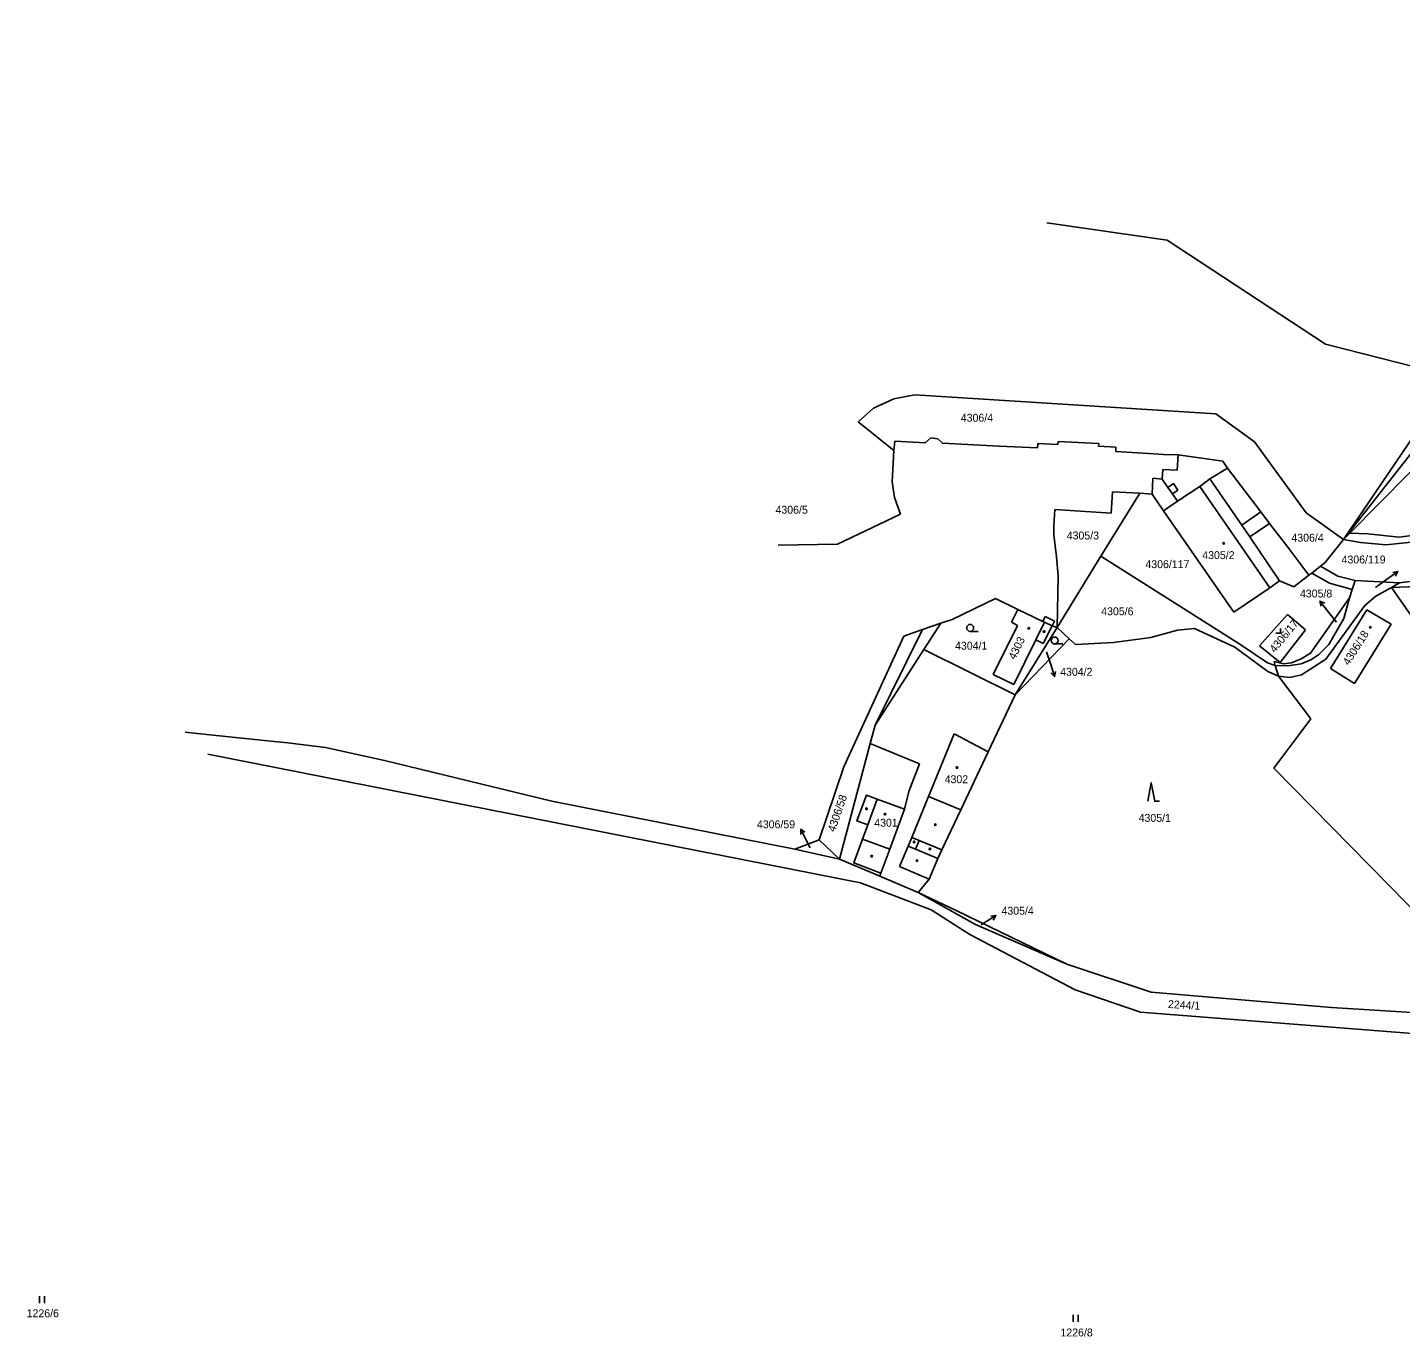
# Model space of a CAD drawing. Extents: x -717507 to -715515, y -957700 to -954941.
# Drawn here: x -717216.2 to -716920.4, y -956686.4 to -956404.4 of the extents above; entities that cross this region are included whole.
import ezdxf

# ---------------------------------------------------------------- set-up
doc = ezdxf.new("R2010")
doc.units = 0
for name, color, linetype in [('Hranice kat_území', 7, 'Continuous'), ('Hranice parcel', 7, 'Continuous'), ('Parcelní čísla', 7, 'Continuous'), ('Pop  PČ popisy', 7, 'Continuous'), ('Vnitřní kresba', 7, 'Continuous'), ('Značky budov', 7, 'Continuous'), ('Značky kultur', 7, 'Continuous')]:
    doc.layers.add(name, color=color, linetype=linetype)

msp = doc.modelspace()

# ---------------------------------------------------------------- linework, layer by layer
at = {"layer": 'Hranice kat_území'}
for points in [[(-717182.2, -956556.2), (-717176.91, -956556.79)], [(-717176.91, -956556.79), (-717168.53, -956557.66)], [(-717168.53, -956557.66), (-717163.78, -956558.15)], [(-717163.78, -956558.15), (-717160.1, -956558.51)], [(-717160.1, -956558.51), (-717152, -956559.57)], [(-717152, -956559.57), (-717139.29, -956562.3)], [(-717139.29, -956562.3), (-717103.19, -956571.1)], [(-717103.19, -956571.1), (-717050.85, -956581.44)], [(-717050.85, -956581.44), (-717041.23, -956583.58)], [(-717041.23, -956583.58), (-717032.56, -956587.24)], [(-717032.56, -956587.24), (-717024.26, -956590.75)], [(-717024.26, -956590.75), (-717011.91, -956597.67)], [(-717011.91, -956597.67), (-716992.25, -956606.23)], [(-716992.25, -956606.23), (-716974.1, -956612.22)], [(-716974.1, -956612.22), (-716935.21, -956615.54)], [(-716935.21, -956615.54), (-716905.16, -956617.42)]]:
    msp.add_lwpolyline(points, dxfattribs=at)
at = {"layer": 'Hranice parcel'}
for points in [[(-716996.56, -956446.46), (-716970.67, -956450.24)], [(-716970.67, -956450.24), (-716936.51, -956472.61)], [(-716936.51, -956472.61), (-716908.87, -956479.65)], [(-716932.64, -956514.75), (-716908.87, -956479.65)], [(-717029.51, -956484.4), (-717025.03, -956483.57)], [(-717025.03, -956483.57), (-716960.17, -956487.66)], [(-717037.23, -956489.38), (-717033.89, -956486.4)], [(-717033.89, -956486.4), (-717029.51, -956484.4)], [(-717037.23, -956489.38), (-717029.51, -956495.58)], [(-716960.17, -956487.66), (-716951.83, -956493.67)], [(-717029.87, -956502.33), (-717029.51, -956495.58)], [(-717029.51, -956495.58), (-717029.3, -956493.53)], [(-717029.3, -956493.53), (-717022.8, -956493.87)], [(-717022.8, -956493.87), (-717021.54, -956492.85)], [(-717021.54, -956492.85), (-717020.03, -956493.02)], [(-717020.03, -956493.02), (-717019.02, -956493.95)], [(-717019.02, -956493.95), (-717006.87, -956494.63)], [(-717006.87, -956494.63), (-716998.6, -956494.98)], [(-716998.6, -956494.98), (-716998.49, -956494.04)], [(-716998.49, -956494.04), (-716994.19, -956494.23)], [(-716994.19, -956494.23), (-716994.16, -956493.63)], [(-716994.16, -956493.63), (-716985.4, -956494.03)], [(-716985.42, -956494.63), (-716985.4, -956494.03)], [(-716985.42, -956494.63), (-716981.67, -956494.8)], [(-716981.73, -956495.79), (-716981.67, -956494.8)], [(-716951.83, -956493.67), (-716940.7, -956508.96)], [(-716931.26, -956513.35), (-716912.39, -956494.22)], [(-716981.73, -956495.79), (-716973.51, -956496.26)], [(-716973.51, -956496.26), (-716971.44, -956496.43)], [(-716971.44, -956496.43), (-716968.28, -956496.47)], [(-716968.51, -956499.79), (-716968.28, -956496.47)], [(-716968.28, -956496.47), (-716958.65, -956497.84)], [(-716958.65, -956497.84), (-716957.64, -956499.36)], [(-716971.73, -956501.72), (-716971.57, -956499.61)], [(-716971.57, -956499.61), (-716968.51, -956499.79)], [(-716957.64, -956499.36), (-716950.48, -956508.76)], [(-717029.87, -956502.33), (-717029.35, -956505.7)], [(-716982.71, -956509.07), (-716982.45, -956504.42)], [(-716982.45, -956504.42), (-716976.56, -956504.75)], [(-716973.85, -956504.96), (-716973.71, -956501.54)], [(-716973.71, -956501.54), (-716971.73, -956501.72)], [(-717029.35, -956505.7), (-717028.07, -956509.25)], [(-716976.56, -956504.75), (-716984.91, -956518.33)], [(-716976.56, -956504.75), (-716973.85, -956504.96)], [(-716973.85, -956504.96), (-716971.4, -956508.52)], [(-717041.69, -956515.75), (-717028.07, -956509.25)], [(-716995.08, -956511.7), (-716994.82, -956508.26)], [(-716994.82, -956508.26), (-716982.71, -956509.07)], [(-716971.4, -956508.52), (-716956.28, -956530.38)], [(-716950.48, -956508.76), (-716948.59, -956511.24)], [(-716940.7, -956508.96), (-716932.64, -956514.75)], [(-716995.08, -956511.7), (-716995.08, -956513.74)], [(-716948.59, -956511.24), (-716944.66, -956516.4)], [(-716932.64, -956514.75), (-716931.26, -956513.35)], [(-716931.26, -956513.35), (-716927.38, -956513.49)], [(-716920.68, -956514.21), (-716911.98, -956513.08)], [(-717054.43, -956515.95), (-717041.69, -956515.75)], [(-716995.08, -956513.74), (-716994.51, -956518.44)], [(-716936.68, -956519.78), (-716932.64, -956514.75)], [(-716927.38, -956513.49), (-716920.68, -956514.21)], [(-716994.51, -956518.44), (-716994.13, -956522.62)], [(-716984.91, -956518.33), (-716994.36, -956533.7)], [(-716984.91, -956518.33), (-716954.99, -956537.24)], [(-716944.66, -956516.4), (-716940.12, -956522.43)], [(-716940.12, -956522.43), (-716939.5, -956521.95)], [(-716939.5, -956521.95), (-716937.58, -956520.45)], [(-716939.5, -956521.95), (-716935.64, -956524.14)], [(-716937.58, -956520.45), (-716936.68, -956519.78)], [(-716994.36, -956533.7), (-716994.13, -956522.62)], [(-716956.28, -956530.38), (-716948.56, -956525.1)], [(-716948.56, -956525.1), (-716946.47, -956523.59)], [(-716946.47, -956523.59), (-716943.35, -956524.91)], [(-716943.35, -956524.91), (-716940.12, -956522.43)], [(-716935.64, -956524.14), (-716930.77, -956525.47)], [(-716930.77, -956525.47), (-716930.12, -956523.58)], [(-716930.12, -956523.58), (-716920.58, -956524.04)], [(-716925.7, -956526.95), (-716922.32, -956525.03)], [(-716922.32, -956525.03), (-716920.58, -956524.04)], [(-716922.32, -956525.03), (-716909.57, -956524.59)], [(-716887.95, -956574.29), (-716922.32, -956525.03)], [(-717016.95, -956531.93), (-717007.65, -956527.44)], [(-717007.65, -956527.44), (-717002.78, -956529.78)], [(-716939.75, -956539.21), (-716931.38, -956527.27)], [(-716932.61, -956531.72), (-716931.38, -956527.27)], [(-716931.38, -956527.27), (-716930.77, -956525.47)], [(-716928.03, -956528.93), (-716925.7, -956526.95)], [(-717004.21, -956532.54), (-717002.78, -956529.78)], [(-717002.78, -956529.78), (-716997.42, -956532.36)], [(-716950.78, -956537.62), (-716944.69, -956530.91)], [(-716944.69, -956530.91), (-716940.81, -956534.16)], [(-716936.49, -956540.53), (-716928.03, -956528.93)], [(-716935.49, -956542.52), (-716927.65, -956529.84)], [(-716927.65, -956529.84), (-716922.42, -956532.99)], [(-717023.34, -956534.08), (-717019.39, -956532.75)], [(-717019.39, -956532.75), (-717016.95, -956531.93)], [(-717008.1, -956543.79), (-717002.88, -956533.23)], [(-717004.21, -956532.54), (-717002.88, -956533.23)], [(-717003.4, -956548.2), (-716994.36, -956533.7)], [(-716997.42, -956532.36), (-716996.93, -956531.33)], [(-716997.33, -956537.11), (-716995.44, -956533.31)], [(-716996.93, -956531.33), (-716994.95, -956532.29)], [(-716995.44, -956533.31), (-716994.95, -956532.29)], [(-716995.44, -956533.31), (-716994.36, -956533.7)], [(-716994.36, -956533.7), (-716991.72, -956536.15)], [(-716968.43, -956534.24), (-716964.76, -956533.88)], [(-716964.76, -956533.88), (-716956.1, -956537.93)], [(-716935.8, -956537.32), (-716932.61, -956531.72)], [(-716930.28, -956545.74), (-716922.42, -956532.99)], [(-717040.28, -956563.7), (-717027.41, -956535.53)], [(-717033.56, -956554.69), (-717023.34, -956534.08)], [(-717027.41, -956535.53), (-717023.34, -956534.08)], [(-717003.7, -956545.96), (-716998.92, -956536.32)], [(-717003.4, -956548.2), (-716991.72, -956536.15)], [(-716998.92, -956536.32), (-716997.33, -956537.11)], [(-716991.72, -956536.15), (-716990.42, -956537.32)], [(-716990.42, -956537.32), (-716982.18, -956536.93)], [(-716982.18, -956536.93), (-716974.15, -956535.83)], [(-716974.15, -956535.83), (-716968.43, -956534.24)], [(-716946.32, -956541.22), (-716940.81, -956534.16)], [(-717033.56, -956554.69), (-717023.07, -956538.44)], [(-717023.07, -956538.44), (-717003.4, -956548.2)], [(-716956.1, -956537.93), (-716948.94, -956543.19)], [(-716954.99, -956537.24), (-716949, -956541.28)], [(-716950.78, -956537.62), (-716946.32, -956541.22)], [(-716941.76, -956540.46), (-716939.75, -956539.21)], [(-716939.7, -956540.67), (-716938.05, -956539.59)], [(-716938.05, -956539.59), (-716935.8, -956537.32)], [(-716949, -956541.28), (-716947.35, -956541.85)], [(-716947.6, -956541.02), (-716945.55, -956541.53)], [(-716947.6, -956541.02), (-716947.35, -956541.85)], [(-716947.35, -956541.85), (-716947.2, -956541.9)], [(-716947.35, -956541.85), (-716946.67, -956544.15)], [(-716947.2, -956541.9), (-716944.63, -956541.96)], [(-716945.55, -956541.53), (-716943.88, -956541.28)], [(-716944.63, -956541.96), (-716941.78, -956541.51)], [(-716943.88, -956541.28), (-716941.76, -956540.46)], [(-716941.78, -956541.51), (-716939.7, -956540.67)], [(-716941.68, -956543.85), (-716936.49, -956540.53)], [(-716935.49, -956542.52), (-716930.28, -956545.74)], [(-717008.1, -956543.79), (-717003.7, -956545.96)], [(-716948.94, -956543.19), (-716946.67, -956544.15)], [(-716946.67, -956544.15), (-716939.7, -956553.33)], [(-716946.67, -956544.15), (-716944.21, -956544.44)], [(-716944.21, -956544.44), (-716941.68, -956543.85)], [(-717009.21, -956560.47), (-717003.4, -956548.2)], [(-717033.56, -956554.69), (-717034.61, -956558.65)], [(-716947.67, -956564), (-716939.7, -956553.33)], [(-717034.61, -956558.65), (-717041.23, -956583.58)], [(-717034.61, -956558.65), (-717023.97, -956563.05)], [(-717015.11, -956572.93), (-717009.21, -956560.47)], [(-717177.33, -956560.98), (-717036.7, -956588.67)], [(-717023.97, -956563.05), (-717026.29, -956569.02)], [(-717045.65, -956579.42), (-717040.28, -956563.7)], [(-716902.29, -956610.17), (-716947.67, -956564)], [(-717026.29, -956569.02), (-717027.23, -956572.85)], [(-717030.41, -956581.43), (-717027.23, -956572.85)], [(-717019.21, -956581.6), (-717015.11, -956572.93)], [(-717050.85, -956581.44), (-717045.65, -956579.42)], [(-717045.65, -956579.42), (-717041.23, -956583.58)], [(-717032.31, -956586.58), (-717030.41, -956581.43)], [(-717021.92, -956587.92), (-717020.02, -956583.47)], [(-717020.02, -956583.47), (-717019.21, -956581.6)], [(-717032.31, -956586.58), (-717032.56, -956587.24)], [(-717036.7, -956588.67), (-717021.5, -956594.54)], [(-717024.26, -956590.75), (-717021.92, -956587.92)], [(-717024.26, -956590.75), (-717016.07, -956594.62)], [(-717021.5, -956594.54), (-717013.15, -956599.83)], [(-717016.07, -956594.62), (-716992.25, -956606.23)], [(-717013.15, -956599.83), (-716990.46, -956611.71)], [(-716990.46, -956611.71), (-716976.38, -956616.58)], [(-716976.38, -956616.58), (-716882.08, -956623.93)]]:
    msp.add_lwpolyline(points, dxfattribs=at)
at = {"layer": 'Pop  PČ popisy'}
for points in [[(-716923.37, -956523.37), (-716920.93, -956521.62)], [(-716922.03, -956521.8), (-716920.93, -956521.62), (-716921.45, -956522.61)], [(-716925.73, -956525.06), (-716923.37, -956523.37)], [(-716935.86, -956530.35), (-716937.72, -956528)], [(-716937.49, -956529.09), (-716937.72, -956528), (-716936.71, -956528.47)], [(-716934.16, -956532.5), (-716935.86, -956530.35)], [(-716996.61, -956538.91), (-716995.81, -956541.41)], [(-716995.81, -956541.41), (-716994.9, -956544.27)], [(-716994.73, -956543.16), (-716994.9, -956544.27), (-716995.68, -956543.47)], [(-717048.25, -956579.82), (-717049.6, -956577.14)], [(-717049.6, -956578.26), (-717049.6, -956577.14), (-717048.7, -956577.81)], [(-717047.57, -956581.17), (-717048.25, -956579.82)], [(-717010.08, -956597.34), (-717007.53, -956595.76)], [(-717008.64, -956595.86), (-717007.53, -956595.76), (-717008.12, -956596.71)], [(-717010.68, -956597.71), (-717010.08, -956597.34)]]:
    msp.add_lwpolyline(points, dxfattribs=at)
at = {"layer": 'Vnitřní kresba'}
for points in [[(-716932.64, -956514.75), (-716846.05, -956404.4)], [(-716961.44, -956501.67), (-716957.64, -956499.36)], [(-716971.73, -956501.72), (-716970.48, -956503.51)], [(-716970.48, -956503.51), (-716969.3, -956502.68)], [(-716970.48, -956503.51), (-716969.52, -956504.89)], [(-716969.52, -956504.89), (-716968.34, -956504.07)], [(-716969.3, -956502.68), (-716968.34, -956504.07)], [(-716968.42, -956506.48), (-716963.57, -956503.28)], [(-716963.57, -956503.28), (-716961.44, -956501.67)], [(-716963.57, -956503.28), (-716948.56, -956525.1)], [(-716961.44, -956501.67), (-716954.59, -956511.65)], [(-716971.4, -956508.52), (-716968.42, -956506.48)], [(-716969.52, -956504.89), (-716968.42, -956506.48)], [(-716954.59, -956511.65), (-716950.48, -956508.76)], [(-716954.59, -956511.65), (-716952.85, -956514.18)], [(-716952.85, -956514.18), (-716948.59, -956511.24)], [(-716952.85, -956514.18), (-716946.47, -956523.59)], [(-716932.64, -956514.75), (-716929.01, -956515.36)], [(-716929.01, -956515.36), (-716923.46, -956515.86)], [(-716923.46, -956515.86), (-716910.56, -956514.53)], [(-716937.58, -956520.45), (-716933.91, -956522.61)], [(-716920.58, -956524.04), (-716901.02, -956521.58)], [(-716933.91, -956522.61), (-716930.12, -956523.58)], [(-717023.07, -956538.44), (-717019.39, -956532.75)], [(-716998.92, -956536.32), (-716997.04, -956532.54)], [(-716997.42, -956532.36), (-716997.04, -956532.54)], [(-716997.04, -956532.54), (-716995.44, -956533.31)], [(-717022.08, -956570.08), (-717016.53, -956556.62)], [(-717016.53, -956556.62), (-717009.21, -956560.47)], [(-717033.1, -956570.68), (-717035.43, -956569.82), (-717037.47, -956575.35), (-717035.15, -956576.22)], [(-717035.15, -956576.22), (-717033.1, -956570.68)], [(-717027.23, -956572.85), (-717033.1, -956570.68)], [(-717025.66, -956578.93), (-717022.08, -956570.08)], [(-717022.08, -956570.08), (-717015.11, -956572.93)], [(-717035.15, -956576.22), (-717036.27, -956579.27)], [(-717036.27, -956579.27), (-717038.18, -956584.41), (-717032.31, -956586.58)], [(-717036.27, -956579.27), (-717030.41, -956581.43)], [(-717028.32, -956585.18), (-717026.44, -956580.79)], [(-717026.44, -956580.79), (-717025.66, -956578.93)], [(-717026.44, -956580.79), (-717024.86, -956581.45)], [(-717025.66, -956578.93), (-717024.08, -956579.59)], [(-717024.86, -956581.45), (-717024.08, -956579.59)], [(-717024.08, -956579.59), (-717019.21, -956581.6)], [(-717024.86, -956581.45), (-717020.02, -956583.47)], [(-717028.32, -956585.18), (-717021.92, -956587.92)]]:
    msp.add_lwpolyline(points, dxfattribs=at)
at = {"layer": 'Značky budov'}
for centre in [(-716958.48, -956515.53), (-717000.45, -956533.85), (-716926.87, -956533.66), (-716997.15, -956534.55), (-717015.92, -956563.85), (-717035.42, -956572.74), (-717031.45, -956573.9), (-717020.58, -956576.14), (-717025.15, -956579.88), (-717021.76, -956581.42), (-717034.3, -956582.95), (-717024.53, -956583.93)]:
    msp.add_circle(centre, 0.175, dxfattribs=at)
at = {"layer": 'Značky kultur'}
for points in [[(-716947.23, -956534.91), (-716946.23, -956534.91), (-716946.23, -956533.91)], [(-717013.08, -956534.51), (-717011.33, -956534.51)], [(-716994.89, -956537.23), (-716993.14, -956537.23)], [(-716974.82, -956571.13), (-716974.07, -956567.13), (-716973.32, -956571.13), (-716972.32, -956571.13)], [(-717213.58, -956679.23), (-717213.58, -956677.73)], [(-717212.54, -956679.23), (-717212.54, -956677.73)], [(-716990.88, -956683.28), (-716990.88, -956681.78)], [(-716989.84, -956683.28), (-716989.84, -956681.78)]]:
    msp.add_lwpolyline(points, dxfattribs=at)
for centre in [(-717013.08, -956533.76), (-716994.89, -956536.48)]:
    msp.add_circle(centre, 0.75, dxfattribs=at)

# ---------------------------------------------------------------- texts
at = {"layer": 'Parcelní čísla'}
for s, p in [('4306/4', (-717015.1, -956489.33)), ('4306/5', (-717055.02, -956509.16)), ('4305/3', (-716992.28, -956514.71)), ('4306/4', (-716943.87, -956515.18)), ('4306/117', (-716975.33, -956520.89)), ('4305/2', (-716963.08, -956518.94)), ('4306/119', (-716933.07, -956519.88)), ('4305/8', (-716942.03, -956527.21)), ('4305/6', (-716984.85, -956531.04)), ('4304/1', (-717016.34, -956538.45)), ('4304/2', (-716993.69, -956544.07)), ('4302', (-717018.58, -956567.22)), ('4306/59', (-717059.02, -956576.94)), ('4301', (-717033.75, -956576.59)), ('4305/1', (-716976.79, -956575.55)), ('4305/4', (-717006.33, -956595.56)), ('1226/6', (-717216.35, -956682.29)), ('1226/8', (-716993.63, -956686.42))]:
    msp.add_text(s, height=1.7, dxfattribs=at).set_placement(p)
for s, rotation, p in [('4306/17', 50.6004, (-716947.46, -956539.23)), ('4303', 63.7005, (-717003.43, -956540.74)), ('4306/18', 57.7005, (-716931.51, -956541.97)), ('4306/58', 71.0006, (-717042.24, -956577.84)), ('2244/1', 356.8028, (-716970.51, -956615.65))]:
    msp.add_text(s, height=1.7, rotation=rotation, dxfattribs=at).set_placement(p)

doc.saveas('drawing.dxf')
